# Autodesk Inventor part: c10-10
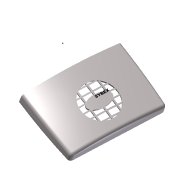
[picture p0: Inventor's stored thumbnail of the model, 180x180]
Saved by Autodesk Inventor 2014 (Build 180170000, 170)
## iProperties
Created: 2010-12
Part Number: c10-10
Material: Generic
Document SubType Name: Modeling
Designer: Thom Tremblay
Density: 1 g/cm^3
Appearance: Generic
Author: Thom Tremblay
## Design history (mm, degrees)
sketch "Sketch1"
  geometry: L1 (-60, -12)-(60, -12); L2 (60, -12)-(60, 12); L3 (60, 12)-(-60, 12); L4 (-60, 12)-(-60, -12); A1 r 350 centre (0, -332.819) between (60, 12) and (-60, 12); A2 r 350 centre (0, 332.819) between (-60, -12) and (60, -12); 3 further points
  constraints: 8 end point, 4 point on circle, 2 centre point, 2 midpoint, 2 parallel, 1 equal radius, 1 horizontal, 1 horizontal alignment, 1 perpendicular, 1 vertical alignment
  dimensions: "d0" = 120 distance of L3.end L2.end; "d1" = 24 distance of L2.end L1.end; "d2" = 350 radius of A1
workplane "Work Plane4"
sketch "Sketch5"
  geometry: L1 (-60, 12)-(-60, -12) reference; L2 (60, -12)-(60, 12) reference; L3 (-58, 10.314)-(-58, -10.314); L4 (58, -10.314)-(58, 10.314); A1 r 350 centre (0, 332.819) between (-60, -12) and (60, -12) reference; A2 r 350 centre (0, -332.819) between (60, 12) and (-60, 12) reference; A3 r 348 centre (0, 332.819) between (-58, -10.314) and (58, -10.314); A4 r 348 centre (0, -332.819) between (58, 10.314) and (-58, 10.314); 1 further point
  constraints: 4 end point, 4 point on circle, 2 centre point, 3 other
  dimensions: "d37" = 2 distance between parallel lines of L2 L4
sketch "Sketch6"
  geometry: L1 (-60, 0)-(60, 0); L2 (60, 0)-(58.843, 22.085); L3 (-60, 0)-(-58.779, 23.307); A1 r 691.758 centre (630.81, -36.204) between (-60, 0) and (-58, -100); A2 r 691.758 centre (-630.81, -36.204) between (58, -100) and (60, 0); 1 further point
  constraints: 6 end point, 4 point on circle, 2 centre point, 2 tangent, 1 horizontal
  dimensions: "d53" = 87 deg angle of L1 L3; "d54" = 87 deg angle of L1 L2 (= d53)
sketch "Sketch7"
  geometry: L1 (17.181, 0)-(12, 0) reference; L2 (15.181, -100)-(10.314, -100) reference; L3 (17.181, 0)-(16.768, 11.838); A1 r 911.322 centre (-893.585, -31.805) between (15.181, -100) and (17.181, 0); 1 further point
  constraints: 2 end point, 2 point on circle, 1 centre point, 1 tangent
  dimensions: "d56" = 88 deg angle of L1 L3
feature "LoftSrf2" sketch "Sketch5", "Sketch6", "Sketch7" dims "d57" = 0, "d58" = 90 deg, "d59" = 0, "d60" = 90 deg, "d61" = 0, "d62" = 90 deg, "d63" = 0, "d64" = 90 deg, "d65" = 0, "d66" = 90 deg
sketch "Sketch2"
  geometry: L1 (-75, -16)-(75, -16); L2 (-75, -60)-(75, -60); A1 r 183.781 centre (0, -183.781) between (75, -16) and (-75, -16); 2 further points
  constraints: 4 end point, 3 point on circle, 1 centre point, 1 coincident, 1 horizontal, 1 parallel
  dimensions: "d5" = 16 distance from line of point (0, 0) L1; "d7" = 60 distance from line of point (0, 0) L2; "d55" = 150 distance of L1.start L1.end
feature "RevolutionSrf1" sketch "Sketch2" dims angle "d8" = 40 deg
patch "Boundary Patch1" dims "d13" = 0, "d67" = 0, "d68" = 0, "d69" = 0, "d70" = 0
workplane "Work Plane1"
sketch "Sketch3"
  geometry: L1 (52, -85)-(52, -73); L2 (38, -73)-(38, -85); A1 r 7 centre (45, -73) between (52, -73) and (38, -73); A2 r 7 centre (45, -85) between (38, -85) and (52, -85); 1 further point
  constraints: 4 end point, 4 point on circle, 4 tangent, 2 centre point, 1 parallel, 1 vertical
  dimensions: "d15" = 12 distance of L1.start L1.end; "d16" = 7 radius of A1; "d50" = 45 horizontal distance of A1.centre point (0, 0); "d51" = 85 vertical distance of point (0, 0) A2.centre
extrude_surface "ExtrusionSrf2" sketch "Sketch3" dims "d19" = 14, "d20" = 5 deg
pattern_linear "Rectangular Pattern1" dims "d23" = 90
workplane "Work Plane2"
feature "Sculpt1"
sketch "Sketch4"
  geometry: L1 (-24.5, 6)-(24.5, 6); L2 (27.5, 3)-(27.5, -3); L3 (24.5, -6)-(-24.5, -6); L4 (-27.5, -3)-(-27.5, 3); A1 r 3 centre (-24.5, 3) between (-24.5, 6) and (-27.5, 3); A2 r 3 centre (24.5, 3) between (27.5, 3) and (24.5, 6); A3 r 3 centre (24.5, -3) between (24.5, -6) and (27.5, -3); A4 r 3 centre (-24.5, -3) between (-27.5, -3) and (-24.5, -6); 6 further points
  constraints: 8 end point, 8 point on circle, 8 tangent, 6 point on line, 4 centre point, 3 equal radius, 2 midpoint, 2 parallel, 1 horizontal, 1 horizontal alignment, 1 perpendicular, 1 vertical alignment
  dimensions: "d28" = 55 distance of point (27.5, -6) point (-27.5, -6); "d29" = 12 distance of point (27.5, 6) point (27.5, -6); "d30" = 3 radius of A1
extrude_surface "ExtrusionSrf6" sketch "Sketch4" dims "d31" = 14, "d32" = 45 deg
patch "Boundary Patch2" dims "d33" = 0, "d34" = 0
fillet "Fillet1" dims "d79" = 4, "d80" = 3, "d81" = 1
feature "Sculpt2"
node "Splitting Plane 1"
shell "Shell1" dims "d83" = 2
split "Split1"
  body "Solid1"
feature "Lip1" dims "d171" = 1, "d172" = 1, "d173" = 0, "d174" = 0, "d175" = 0, "d176" = 0
feature "Lip2" dims "d177" = 1, "d178" = 1, "d179" = 0, "d180" = 0, "d181" = 0, "d182" = 0.5
split "Split3"
  node "Back"
sketch "Sketch9"
  geometry: L1 (50.167, -73)-(50.167, -85) reference; L2 (39.833, -85)-(39.833, -73) reference; L3 (45, -73)-(45, -85); L4 (45, -85)-(39.833, -85); A1 r 5.167 centre (45, -73) between (50.167, -73) and (39.833, -73) reference; A2 r 5.167 centre (45, -85) between (39.833, -85) and (50.167, -85) reference; 5 further points
  constraints: 4 end point, 1 horizontal, 1 midpoint, 1 parallel, 1 perpendicular, 1 vertical, 3 other
  dimensions: "d86" = 90 distance of point (45, -79) point (-45, -79); "d89" = 40 distance of point (45, -79) point (45, -39)
  node "Projected Loop1"
feature "Boss1" dims "d92" = 0, "d93" = 0, "d94" = 7, "d95" = 2, "d96" = 0.5, "d97" = 6, "d98" = 1.25, "d99" = 3.5, "d100" = 2.5 deg, "d101" = 2.5 deg, "d102" = 2.5 deg, "d103" = 2.5 deg, "d104" = 90 deg, "d107" = 2, "d108" = 2, "d109" = 10, "d110" = 0, "d111" = 10 deg, "d112" = 2.5 deg, "d113" = 0, "d114" = 0, "d115" = 0, "d116" = 360 deg
feature "Boss2" dims "d117" = 3, "d118" = 0, "d119" = 6, "d120" = 3, "d121" = 9.5, "d122" = 2 deg, "d123" = 1 deg, "d126" = 2, "d127" = 2, "d128" = 10, "d129" = 0, "d130" = 10 deg, "d131" = 2.5 deg, "d132" = 0, "d133" = 0, "d134" = 0, "d135" = 360 deg
workplane "Work Plane6"
sketch "Sketch10"
  geometry: L1 (24, -85)-(-24, -85); L2 (-30, -79)-(-30, -51); L3 (-24, -45)-(24, -45); L4 (30, -51)-(30, -79); L5 (54.344, -100)-(-54.344, -100) reference; A1 r 6 centre (-24, -51) between (-24, -45) and (-30, -51); A2 r 6 centre (24, -51) between (30, -51) and (24, -45); A3 r 6 centre (24, -79) between (24, -85) and (30, -79); A4 r 6 centre (-24, -79) between (-30, -79) and (-24, -85); 5 further points
  constraints: 8 end point, 8 point on circle, 8 tangent, 6 point on line, 4 centre point, 3 equal radius, 2 parallel, 1 horizontal, 1 midpoint, 1 perpendicular, 1 vertical alignment
  dimensions: "d137" = 60 distance of point (-30, -45) point (30, -45); "d138" = 40 distance of point (-30, -85) point (-30, -45); "d139" = 15 distance between parallel lines of L5 L1; "d141" = 6 radius of A2
feature "Rest1" sketch "Sketch10" dims "d142" = 5, "d143" = 0, "d144" = 0, "d145" = 0, "d146" = 2 deg, "d147" = 2 deg, "d148" = 2
feature "Rule Fillet1" dims "d149" = 2, "d150" = 1
workplane "Work Plane7"
sketch "Sketch11" dims "d154" = 16, "d155" = 8, "d161" = 10, "d168" = 10
  geometry: L1 (-13, -39.858)-(-13, -90.142); L2 (-25.187, -85)-(29.449, -85); L3 (0, -39.858)-(0, -90.142); L4 (13, -39.858)-(13, -90.142); L5 (-25.187, -77)-(29.449, -77); L6 (-25.187, -69)-(29.449, -69); L7 (-25.187, -61)-(29.449, -61); L8 (-25.187, -53)-(29.449, -53); L9 (-25.187, -45)-(29.449, -45); C1 r 22.5 at (0, -65); 3 further points; 1 other entity
  constraints: 18 end point, 2 coincident, 2 vertical, 1 centre point, 1 horizontal, 1 midpoint, 1 perpendicular, 1 vertical alignment, 23 other
  dimensions: "d152" = 45 diameter of C1; "d153" = 65 distance of point (0, 0) C1.centre; "d158" = 13 distance of L1.start L3.start; "d165" = 8 distance of L2.start L5.start; "d170" = 4 distance from line of L7 point (0, -65)
feature "Grill1" sketch "Sketch11" dims "d185" = 2, "d186" = 0, "d187" = 1, "d188" = 2, "d189" = 0, "d190" = 1, "d191" = 0.5, "d192" = 0, "d193" = 2, "d194" = 1, "d195" = 0, "d196" = 0, "d197" = 88.84493
sketch "Sketch12"
  geometry: L1 (-12.481, -61.203)-(12.401, -61.203); L2 (12.401, -61.203)-(12.401, -68.714); L3 (12.401, -68.714)-(-12.481, -68.714); L4 (-12.481, -68.714)-(-12.481, -61.203); 1 further point
  constraints: 2 other
body "Srf2"
body "Srf3"
body "Srf4"
body "Srf5"
body "Srf6"
body "Srf7"
body "Srf8"
body "Srf9"
body "Srf11"
feature "Stitch Surface1"
body "Srf12"
extrude_surface "ExtrusionSrf3"
extrude_surface "ExtrusionSrf4"
extrude_surface "ExtrusionSrf5"
node "Front"
node "Back - Top"
node "Back - Bottom"
other parameters: "d14" = -24, "d52" = -6, "d183" = 1, "d184" = 2
